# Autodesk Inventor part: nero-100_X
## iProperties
Shininess: 20.0
Length Units: 11269
Angle Units: 11279
Time Units: 11290
Mass Units: 11283
Length Display Precision: 2
Angle Display Precision: 2
Part Number: nero-100_X
Material: Nichtrostender Stahl - 440C
Document SubType Name: Modellieren
Description: Ipc-25 /CXX/M18
Checked By: Alves
Created: 2005-08
Designer: Ohle
Manufacturer: Standard
Standards Organization: Custom
Density: 0.0
Volumn: 0.0
Area: 0.0
PropertySet Name: Model Information
Control State: 0
Master: False
Checked Out: False
BESTELLNUMMER: Ipc-25 /CXX/M18
ME: ST
Title: Ipc Sensoren
Author: Ohle
Comments: keine Bemerkung
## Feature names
1. Grundkörper pico+ [Revolution]
2. Pole [Extrusion]
3. Rundung Pole [Fillet]
4. Verdrehsicherung [Extrusion]
5. Bohrung Ausrichtung [Extrusion]
